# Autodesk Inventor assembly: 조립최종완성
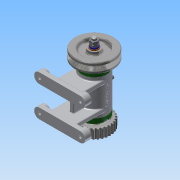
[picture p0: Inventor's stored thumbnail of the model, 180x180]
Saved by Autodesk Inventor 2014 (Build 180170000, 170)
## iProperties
Created: 2015-11
Part Number: 조립최종완성
Document SubType Name: Assembly
Designer: 27
Author: 27
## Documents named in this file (16)
- C:\Users\27\Desktop\451110V1019\조립최종완성.iam
- C:\Users\27\Desktop\451110V1019\1-본체.ipt
- C:\Users\27\Desktop\451110V1019\베어링 15 x 32 x 9.ipt
- C:\Users\27\Desktop\451110V1019\축.ipt
- C:\Users\27\Desktop\451110V1019\키 3 x 3 x 12.ipt
- C:\Users\27\Desktop\451110V1019\커버.ipt
- C:\Users\27\Desktop\451110V1019\오일 실 15 25 7.ipt
- C:\Users\27\Desktop\451110V1019\V벨트풀리.ipt
- C:\Users\27\Desktop\451110V1019\스퍼기어.ipt
- C:\Users\27\Desktop\451110V1019\와셔 8x17.ipt
- C:\Users\27\Desktop\451110V1019\스프링와셔 8.ipt
- C:\Users\27\Desktop\451110V1019\너트 M 8.ipt
- C:\Users\27\Desktop\451110V1019\볼트 M4 x 12.ipt
- C:\Users\27\Desktop\451110V1019\니플 M 6 x 0.75.ipt
- C:\Users\27\Desktop\451110V1019\볼트 M 6 x 8.ipt
- C:\Users\27\Desktop\451110V1019\와셔 6x11.5.ipt
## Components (12 placed, 4 different names)
1. 1-본체:1 — 각도:5, 각도:6, 각도:7, 각도:8, 각도:9, 각도:10, 각도:11, 각도:12, 각도:13, 각도:14, 각도:15
2. KS B 2023 6002 - 15 x 32 x 9:1
3. KS B 2023 6002 - 15 x 32 x 9:2
4. V벨트풀리:1 — 각도:3
5. ISO 4762 M4 x 12:1
6. ISO 4762 M4 x 12:3
7. ISO 4762 M4 x 12:4
8. ISO 4762 M4 x 12:5
9. ISO 4762 M4 x 12:2
10. ISO 4762 M4 x 12:6
11. ISO 4762 M4 x 12:7
12. ISO 4762 M4 x 12:8
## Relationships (12: Angle 12)
- 각도:3 [Angle]: V벨트풀리:1
- 각도:5 [Angle]: 1-본체:1
- 각도:6 [Angle]: 1-본체:1
- 각도:7 [Angle]: 1-본체:1
- 각도:8 [Angle]: 1-본체:1
- 각도:9 [Angle]: 1-본체:1
- 각도:10 [Angle]: 1-본체:1
- 각도:11 [Angle]: 1-본체:1
- 각도:12 [Angle]: 1-본체:1
- 각도:13 [Angle]: 1-본체:1
- 각도:14 [Angle]: 1-본체:1
- 각도:15 [Angle]: 1-본체:1
